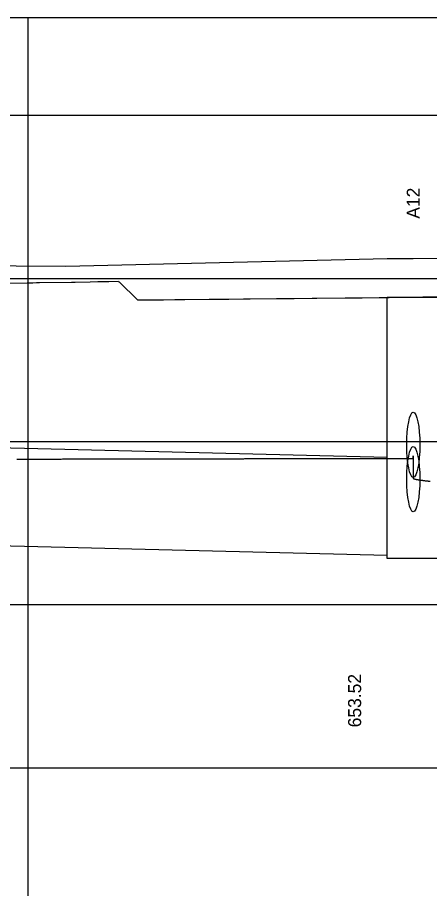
# Model space of a CAD drawing. Extents: x 2252703 to 2264864, y 13787568 to 13790989.
# Drawn here: x 2258110.4 to 2258173.6, y 13790832 to 13790965.5 of the extents above; entities that cross this region are included whole.
import ezdxf

# ---------------------------------------------------------------- set-up
doc = ezdxf.new("R2010")
doc.units = 0
for name, color, linetype in [('blank4', 7, 'Continuous'), ('D_DRN_PROF_HGL', 7, 'Continuous'), ('D_PROF_1', 7, 'Continuous'), ('D_PROF_NOTES_1', 7, 'Continuous'), ('Default', 7, 'Continuous'), ('Drain_PipeInside', 7, 'Continuous'), ('E_Terrain', 7, 'Continuous'), ('Inlet', 7, 'Continuous'), ('z - Construction', 7, 'Continuous')]:
    doc.layers.add(name, color=color, linetype=linetype)

msp = doc.modelspace()

# ---------------------------------------------------------------- linework, layer by layer
at = {"layer": 'blank4'}
msp.add_lwpolyline([(2257912.03, 13790700.51), (2257912.03, 13790965.51), (2261066.03, 13790965.51), (2261066.03, 13790700.51)], close=True, dxfattribs=at)
at = {"layer": 'D_DRN_PROF_HGL'}
msp.add_line((2258171.1, 13790897.92), (2258171.1, 13790898.32), dxfattribs=at)
for points in [[(2258110.28, 13790897.82), (2258110.47, 13790897.82), (2258110.65, 13790897.82), (2258110.83, 13790897.82), (2258111.02, 13790897.82), (2258111.2, 13790897.82), (2258111.38, 13790897.82), (2258111.57, 13790897.82), (2258111.75, 13790897.82), (2258111.94, 13790897.82), (2258112.12, 13790897.82), (2258112.3, 13790897.82), (2258112.49, 13790897.82), (2258112.67, 13790897.83), (2258112.85, 13790897.83), (2258113.04, 13790897.83), (2258113.22, 13790897.83), (2258113.41, 13790897.83), (2258113.59, 13790897.83), (2258113.77, 13790897.83), (2258113.96, 13790897.83), (2258114.14, 13790897.83), (2258114.33, 13790897.83), (2258114.51, 13790897.83), (2258114.7, 13790897.83), (2258114.88, 13790897.83), (2258115.06, 13790897.83), (2258115.25, 13790897.83), (2258115.43, 13790897.83), (2258115.62, 13790897.83), (2258115.8, 13790897.83), (2258115.99, 13790897.83), (2258116.17, 13790897.83), (2258116.36, 13790897.83), (2258116.54, 13790897.83), (2258116.72, 13790897.83), (2258116.91, 13790897.83), (2258117.09, 13790897.83), (2258117.28, 13790897.84), (2258117.46, 13790897.84), (2258117.65, 13790897.84), (2258117.83, 13790897.84), (2258118.02, 13790897.84), (2258118.2, 13790897.84), (2258118.39, 13790897.84), (2258118.57, 13790897.84), (2258118.76, 13790897.84), (2258118.94, 13790897.84), (2258119.13, 13790897.84), (2258119.31, 13790897.84), (2258119.5, 13790897.84), (2258119.68, 13790897.84), (2258119.87, 13790897.84), (2258120.05, 13790897.84), (2258120.24, 13790897.84), (2258120.42, 13790897.84), (2258120.61, 13790897.84), (2258120.79, 13790897.84), (2258120.98, 13790897.84), (2258121.16, 13790897.84), (2258121.35, 13790897.84), (2258121.53, 13790897.84), (2258121.72, 13790897.84), (2258121.9, 13790897.84), (2258122.09, 13790897.84), (2258122.28, 13790897.85), (2258122.46, 13790897.85), (2258122.65, 13790897.85), (2258122.83, 13790897.85), (2258123.02, 13790897.85), (2258123.2, 13790897.85), (2258123.39, 13790897.85), (2258123.57, 13790897.85), (2258123.76, 13790897.85), (2258123.95, 13790897.85), (2258124.13, 13790897.85), (2258124.32, 13790897.85), (2258124.5, 13790897.85), (2258124.69, 13790897.85), (2258124.87, 13790897.85), (2258125.06, 13790897.85), (2258125.25, 13790897.85), (2258125.43, 13790897.85), (2258125.62, 13790897.85), (2258125.8, 13790897.85), (2258125.99, 13790897.85), (2258126.18, 13790897.85), (2258126.36, 13790897.85), (2258126.55, 13790897.85), (2258126.73, 13790897.85), (2258126.92, 13790897.85), (2258127.11, 13790897.85), (2258127.29, 13790897.85), (2258127.48, 13790897.86), (2258127.67, 13790897.86), (2258127.85, 13790897.86), (2258128.04, 13790897.86), (2258128.22, 13790897.86), (2258128.41, 13790897.86), (2258128.6, 13790897.86), (2258128.78, 13790897.86), (2258128.97, 13790897.86), (2258129.16, 13790897.86), (2258129.34, 13790897.86), (2258129.53, 13790897.86), (2258129.72, 13790897.86), (2258129.9, 13790897.86), (2258130.09, 13790897.86), (2258130.28, 13790897.86), (2258130.46, 13790897.86), (2258130.65, 13790897.86), (2258130.84, 13790897.86), (2258131.02, 13790897.86), (2258131.21, 13790897.86), (2258131.4, 13790897.86), (2258131.58, 13790897.86), (2258131.77, 13790897.86), (2258131.96, 13790897.86), (2258132.14, 13790897.86), (2258132.33, 13790897.86), (2258132.52, 13790897.86), (2258132.7, 13790897.86), (2258132.89, 13790897.86), (2258133.08, 13790897.87), (2258133.26, 13790897.87), (2258133.45, 13790897.87), (2258133.64, 13790897.87), (2258133.83, 13790897.87), (2258134.01, 13790897.87), (2258134.2, 13790897.87), (2258134.39, 13790897.87), (2258134.57, 13790897.87), (2258134.76, 13790897.87), (2258134.95, 13790897.87), (2258135.14, 13790897.87), (2258135.32, 13790897.87), (2258135.51, 13790897.87), (2258135.7, 13790897.87), (2258135.89, 13790897.87), (2258136.07, 13790897.87), (2258136.26, 13790897.87), (2258136.45, 13790897.87), (2258136.63, 13790897.87), (2258136.82, 13790897.87), (2258137.01, 13790897.87), (2258137.2, 13790897.87), (2258137.38, 13790897.87), (2258137.57, 13790897.87), (2258137.76, 13790897.87), (2258137.95, 13790897.87), (2258138.14, 13790897.87), (2258138.32, 13790897.87), (2258138.51, 13790897.87), (2258138.7, 13790897.87), (2258138.89, 13790897.87), (2258139.07, 13790897.88), (2258139.26, 13790897.88), (2258139.45, 13790897.88), (2258139.64, 13790897.88), (2258139.82, 13790897.88), (2258140.01, 13790897.88), (2258140.2, 13790897.88), (2258140.39, 13790897.88), (2258140.58, 13790897.88), (2258140.76, 13790897.88), (2258140.95, 13790897.88), (2258141.14, 13790897.88), (2258141.33, 13790897.88), (2258141.52, 13790897.88), (2258141.7, 13790897.88), (2258141.89, 13790897.88), (2258142.08, 13790897.88), (2258142.27, 13790897.88), (2258142.46, 13790897.88), (2258142.65, 13790897.88), (2258142.83, 13790897.88), (2258143.02, 13790897.88), (2258143.21, 13790897.88), (2258143.4, 13790897.88), (2258143.59, 13790897.88), (2258143.77, 13790897.88), (2258143.96, 13790897.88), (2258144.15, 13790897.88), (2258144.34, 13790897.88), (2258144.53, 13790897.88), (2258144.72, 13790897.88), (2258144.9, 13790897.88), (2258145.09, 13790897.88), (2258145.28, 13790897.89), (2258145.47, 13790897.89), (2258145.66, 13790897.89), (2258145.85, 13790897.89), (2258146.04, 13790897.89), (2258146.22, 13790897.89), (2258146.41, 13790897.89), (2258146.6, 13790897.89), (2258146.79, 13790897.89), (2258146.98, 13790897.89), (2258147.17, 13790897.89), (2258147.36, 13790897.89), (2258147.55, 13790897.89), (2258147.73, 13790897.89), (2258147.92, 13790897.89), (2258148.11, 13790897.89), (2258148.3, 13790897.89), (2258148.49, 13790897.89), (2258148.68, 13790897.89), (2258148.87, 13790897.89), (2258149.06, 13790897.89), (2258149.24, 13790897.89), (2258149.43, 13790897.89), (2258149.62, 13790897.89), (2258149.81, 13790897.89), (2258150, 13790897.89), (2258150.19, 13790897.89), (2258150.38, 13790897.89), (2258150.57, 13790897.89), (2258150.76, 13790897.89), (2258150.95, 13790897.89), (2258151.14, 13790897.89), (2258151.32, 13790897.89), (2258151.51, 13790897.89), (2258151.7, 13790897.89), (2258151.89, 13790897.89), (2258152.08, 13790897.9), (2258152.27, 13790897.9), (2258152.46, 13790897.9), (2258152.65, 13790897.9), (2258152.84, 13790897.9), (2258153.03, 13790897.9), (2258153.22, 13790897.9), (2258153.41, 13790897.9), (2258153.6, 13790897.9), (2258153.79, 13790897.9), (2258153.97, 13790897.9), (2258154.16, 13790897.9), (2258154.35, 13790897.9), (2258154.54, 13790897.9), (2258154.73, 13790897.9), (2258154.92, 13790897.9), (2258155.11, 13790897.9), (2258155.3, 13790897.9), (2258155.49, 13790897.9), (2258155.68, 13790897.9), (2258155.87, 13790897.9), (2258156.06, 13790897.9), (2258156.25, 13790897.9), (2258156.44, 13790897.9), (2258156.63, 13790897.9), (2258156.82, 13790897.9), (2258157.01, 13790897.9), (2258157.2, 13790897.9), (2258157.39, 13790897.9), (2258157.58, 13790897.9), (2258157.77, 13790897.9), (2258157.96, 13790897.9), (2258158.15, 13790897.9), (2258158.34, 13790897.9), (2258158.53, 13790897.9), (2258158.72, 13790897.9), (2258158.91, 13790897.9), (2258159.1, 13790897.9), (2258159.29, 13790897.9), (2258159.48, 13790897.91), (2258159.67, 13790897.91), (2258159.86, 13790897.91), (2258160.05, 13790897.91), (2258160.24, 13790897.91), (2258160.43, 13790897.91), (2258160.62, 13790897.91), (2258160.81, 13790897.91), (2258161, 13790897.91), (2258161.19, 13790897.91), (2258161.38, 13790897.91), (2258161.57, 13790897.91), (2258161.76, 13790897.91), (2258161.95, 13790897.91), (2258162.14, 13790897.91), (2258162.33, 13790897.91), (2258162.52, 13790897.91), (2258162.71, 13790897.91), (2258162.9, 13790897.91), (2258163.09, 13790897.91), (2258163.28, 13790897.91), (2258163.47, 13790897.91), (2258163.66, 13790897.91), (2258163.85, 13790897.91), (2258164.04, 13790897.91), (2258164.23, 13790897.91), (2258164.42, 13790897.91), (2258164.61, 13790897.91), (2258164.8, 13790897.91), (2258164.99, 13790897.91), (2258165.18, 13790897.91), (2258165.37, 13790897.91), (2258165.57, 13790897.91), (2258165.76, 13790897.91), (2258165.95, 13790897.91), (2258166.14, 13790897.91), (2258166.33, 13790897.91), (2258166.52, 13790897.91), (2258166.71, 13790897.91), (2258166.9, 13790897.91), (2258167.09, 13790897.91), (2258167.28, 13790897.92), (2258167.47, 13790897.92), (2258167.66, 13790897.92), (2258167.85, 13790897.92), (2258168.04, 13790897.92), (2258168.24, 13790897.92), (2258168.43, 13790897.92), (2258168.62, 13790897.92), (2258168.81, 13790897.92), (2258169, 13790897.92), (2258169.19, 13790897.92), (2258169.38, 13790897.92), (2258169.57, 13790897.92), (2258169.76, 13790897.92), (2258169.95, 13790897.92), (2258170.14, 13790897.92), (2258170.33, 13790897.92), (2258170.53, 13790897.92), (2258170.72, 13790897.92), (2258170.91, 13790897.92), (2258171.1, 13790897.92)], [(2258171.1, 13790898.32), (2258171.1, 13790894.87), (2258171.1, 13790894.86), (2258171.1, 13790894.86), (2258171.1, 13790894.85), (2258171.11, 13790894.85), (2258171.11, 13790894.84), (2258171.12, 13790894.84), (2258171.13, 13790894.83), (2258171.13, 13790894.83), (2258171.14, 13790894.82), (2258171.15, 13790894.82), (2258171.17, 13790894.81), (2258171.18, 13790894.81), (2258171.19, 13790894.8), (2258171.21, 13790894.79), (2258171.23, 13790894.79), (2258171.24, 13790894.78), (2258171.26, 13790894.78), (2258171.28, 13790894.77), (2258171.31, 13790894.76), (2258171.33, 13790894.76), (2258171.35, 13790894.75), (2258171.38, 13790894.75), (2258171.41, 13790894.74), (2258171.43, 13790894.73), (2258171.46, 13790894.73), (2258171.5, 13790894.72), (2258171.53, 13790894.71), (2258171.56, 13790894.71), (2258171.6, 13790894.7), (2258171.63, 13790894.69), (2258171.67, 13790894.69), (2258171.71, 13790894.68), (2258171.75, 13790894.67), (2258171.8, 13790894.67), (2258171.84, 13790894.66), (2258171.89, 13790894.65), (2258171.93, 13790894.64), (2258171.98, 13790894.64), (2258172.03, 13790894.63), (2258172.08, 13790894.62), (2258172.14, 13790894.61), (2258172.19, 13790894.61), (2258172.25, 13790894.6), (2258172.31, 13790894.59), (2258172.37, 13790894.58), (2258172.43, 13790894.57), (2258172.49, 13790894.57), (2258172.56, 13790894.56), (2258172.63, 13790894.55), (2258172.7, 13790894.54), (2258172.77, 13790894.53), (2258172.84, 13790894.52), (2258172.91, 13790894.51), (2258172.99, 13790894.51), (2258173.07, 13790894.5), (2258173.15, 13790894.49), (2258173.23, 13790894.48), (2258173.31, 13790894.47), (2258173.4, 13790894.46), (2258173.49, 13790894.45), (2258173.58, 13790894.44), (2258173.67, 13790894.43)]]:
    msp.add_lwpolyline(points, dxfattribs=at)
at = {"layer": 'D_PROF_1'}
msp.add_lwpolyline([(2258109.15, 13790924.8), (2258111.86, 13790924.83), (2258111.89, 13790924.83), (2258112.64, 13790924.84), (2258112.7, 13790924.84), (2258112.7, 13790924.84), (2258112.72, 13790924.85), (2258113.3, 13790924.86), (2258113.31, 13790924.86), (2258113.63, 13790924.86), (2258113.78, 13790924.86), (2258118.66, 13790924.95), (2258118.66, 13790924.95), (2258119.2, 13790924.96), (2258119.2, 13790924.96), (2258119.24, 13790924.96), (2258121.52, 13790925), (2258122.73, 13790925.02), (2258123.21, 13790925.03), (2258123.93, 13790925.04), (2258124.39, 13790925.05), (2258125.87, 13790925.07), (2258125.95, 13790924.99), (2258126.01, 13790924.93), (2258128.78, 13790922.21), (2258129.19, 13790922.21), (2258129.19, 13790922.21), (2258132.72, 13790922.25), (2258132.76, 13790922.25), (2258134.53, 13790922.26), (2258134.57, 13790922.26), (2258136.01, 13790922.28), (2258136.04, 13790922.28), (2258139.81, 13790922.31), (2258139.95, 13790922.32), (2258140.56, 13790922.32), (2258140.58, 13790922.32), (2258142.69, 13790922.34), (2258142.79, 13790922.34), (2258145.07, 13790922.36), (2258145.2, 13790922.37), (2258145.25, 13790922.37), (2258146.07, 13790922.37), (2258150.13, 13790922.41), (2258150.43, 13790922.42), (2258152.64, 13790922.44), (2258152.82, 13790922.44), (2258155.57, 13790922.47), (2258155.83, 13790922.47), (2258155.87, 13790922.47), (2258156.31, 13790922.47), (2258160.64, 13790922.51), (2258161.14, 13790922.52), (2258162.38, 13790922.53), (2258162.54, 13790922.53), (2258162.56, 13790922.53), (2258162.74, 13790922.53), (2258162.74, 13790922.53), (2258162.79, 13790922.54), (2258162.79, 13790922.54), (2258162.83, 13790922.54), (2258162.84, 13790922.54), (2258162.96, 13790922.54), (2258163.28, 13790922.54), (2258165.87, 13790922.57), (2258165.9, 13790922.57), (2258166.11, 13790922.57), (2258166.12, 13790922.57), (2258166.2, 13790922.57), (2258166.21, 13790922.57), (2258166.28, 13790922.57), (2258166.35, 13790922.57), (2258166.84, 13790922.58), (2258167.1, 13790922.58), (2258167.1, 13790922.58), (2258167.42, 13790922.58), (2258171.1, 13790922.65), (2258171.1, 13790922.65), (2258171.42, 13790922.65), (2258171.57, 13790922.66), (2258172.57, 13790922.67), (2258173.06, 13790922.68), (2258175.1, 13790922.72)], dxfattribs=at)
at = {"layer": 'Default'}
msp.add_line((2258112.03, 13790700.51), (2258112.03, 13790965.51), dxfattribs=at)
at = {"layer": 'Drain_PipeInside'}
for p, q in [((2258039.75, 13790901.28), (2258167.1, 13790898.09)), ((2258039.75, 13790886.28), (2258167.1, 13790883.09))]:
    msp.add_line(p, q, dxfattribs=at)
for centre in [(2258171.1, 13790900), (2258171.1, 13790894.74)]:
    msp.add_ellipse(centre, major_axis=(0, 5), ratio=0.2, dxfattribs=at)
at = {"layer": 'E_Terrain'}
msp.add_lwpolyline([(2257912.03, 13790918.85), (2257912.85, 13790918.87), (2257916.74, 13790924.34), (2257917.27, 13790924.5), (2257917.38, 13790924.97), (2257927.53, 13790925.73), (2257931.04, 13790925.9), (2257939.15, 13790926.11), (2257950.87, 13790926.84), (2258000.4, 13790926.04), (2258031.75, 13790926.72), (2258031.75, 13790926.72), (2258035.75, 13790926.73), (2258035.75, 13790926.73), (2258039.75, 13790926.75), (2258039.75, 13790926.75), (2258051.14, 13790926.91), (2258102.49, 13790927.48), (2258117.81, 13790927.41), (2258167.1, 13790928.54), (2258167.1, 13790928.54), (2258171.1, 13790928.56), (2258171.1, 13790928.56), (2258175.1, 13790928.59)], dxfattribs=at)
at = {"layer": 'Inlet'}
msp.add_lwpolyline([(2258167.1, 13790922.65), (2258175.1, 13790922.65), (2258175.1, 13790882.59), (2258167.1, 13790882.59)], close=True, dxfattribs=at)
at = {"layer": 'z - Construction'}
for p, q in [((2257912.03, 13790950.51), (2261066.03, 13790950.51)), ((2257912.03, 13790925.51), (2261066.03, 13790925.51)), ((2257912.03, 13790900.51), (2261066.03, 13790900.51)), ((2257912.03, 13790875.51), (2261066.03, 13790875.51)), ((2257912.03, 13790850.51), (2261066.03, 13790850.51))]:
    msp.add_line(p, q, dxfattribs=at)

# ---------------------------------------------------------------- texts
at = {"layer": 'D_PROF_NOTES_1'}
for s, p in [('A12', (2258172.1, 13790934.66)), ('653.52', (2258163.1, 13790856.71))]:
    msp.add_text(s, height=2, rotation=90, dxfattribs=at).set_placement(p)

doc.saveas('drawing.dxf')
